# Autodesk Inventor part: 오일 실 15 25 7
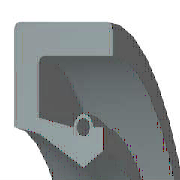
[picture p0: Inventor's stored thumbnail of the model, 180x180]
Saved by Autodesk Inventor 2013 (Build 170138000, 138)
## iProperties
IsCustomPart: 1
Created: 2012-02
Part Number: 오일 실 15 25 7
Material: 고무
Description: 오일 실 - 스프링 장착, 금속 케이스 SM
Document SubType Name: Modeling
Standard: JIS B 2402
Designer: mdu-01
Standards Organization: JIS
Language: ko-KR
Size Designation: 15 25 7 A
Categories: <MemberInstance><Categories><Category DisplayName="샤프트 부품" InternalName="7f7aeb1f-a693-4053-b835-cee3144e0d98" Mnemonic="SHFT"><Category DisplayName="실링" Intern
Density: 0.93 g/cm^3
Author: mdu-01
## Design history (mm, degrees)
body "Solid1"
revolve "회전1" stored, may be unused: angle "d33" = 360 deg
fillet "모깎기1" dims "d34" = 0.35 (= 0.05 x b)
chamfer "모따기1" distance "d35" = 0.7 (= 0.1 x b); stored, may be unused: second distance "d36" = 0.35 (= 0.05 x b), angle "d41" = 45 deg
sketch "스케치2"
  geometry: L1 (8.714, -5.158)-(9.184, -7); L2 (8.214, -4.55)-(8.714, -5.158); L3 (7.5, -1.75)-(8.214, -4.55); L4 (8.167, -0.875)-(7.5, -1.75); L5 (9.284, -0.875)-(8.167, -0.875); L6 (9.284, -1.575)-(9.284, -0.875); L7 (9.284, -5.25)-(9.284, -2.975); L8 (10.5, -5.25)-(9.284, -5.25); L9 (11.5, -1.75)-(10.5, -5.25); L10 (11.5, 0)-(11.5, -1.75); L11 (12.5, 0)-(11.5, 0); L12 (12.5, -7)-(12.5, 0); L13 (9.184, -7)-(12.5, -7); L14 (0, -9.6)-(0, 1.6) reference; L15 (28, 0)-(14, 0) reference; A1 r 0.7 centre (9.284, -2.275) between (9.284, -2.975) and (9.284, -1.575)
  constraints: 26 end point, 4 horizontal, 4 vertical, 2 point on circle, 1 centre point, 1 collinear, 1 parallel
  dimensions: "d2" = 7 distance of L12.start L11.start (= b); "d4" = 0.875 vertical distance of L10.start L5.start (= 0.125 x b); "d6" = 1 distance of L11.start L10.start (= 0.1 x dd - 0.1 x Diam); "d8" = 1.75 distance of L10.start L9.start (= 0.25 x b); "d10" = 1.75 vertical distance of L8.start L1.end (= 0.25 x b); "d12" = 1 horizontal distance of L9.start L8.start (= 0.1 x dd - 0.1 x Diam); "d14" = 0.7 radius of A1 (= 0.1 x b); "d16" = 0 horizontal distance of A1.centre L7.end; "d18" = 0.7 distance of L6.start L5.start (= 0.1 x b); "d20" = 0.66667 horizontal distance of L4.start L3.start (= 0.0666667 x dd - 0.0666667 x Diam); "d22" = 0.1 horizontal distance of L7.start L1.end (= 0.01 x dd - 0.01 x Diam); "d24" = 0.875 vertical distance of L4.start L3.start (= 0.125 x b); "d26" = 2.8 vertical distance of L3.start L2.start (= 0.4 x b); "d28" = 0.71429 horizontal distance of L3.start L2.start (= 0.0714286 x dd - 0.0714286 x Diam); "d30" = 1.84211 vertical distance of L1.start L1.end (= 0.263158 x b); "d32" = 0.5 horizontal distance of L2.start L1.start (= 0.05 x dd - 0.05 x Diam); "d37" = 0 distance between parallel lines of L15 L11; "d38" = 12.5 distance between parallel lines of L14 L12 (= 0.5 x dd); "d39" = 7.5 distance from line of L14 L3.start (= 0.5 x Diam)
other parameters: "dd" = 25 [user parameter; used in 7 equation terms], "Diam" = 15 [user parameter; used in 7 equation terms], "b" = 7 [user parameter; used in 12 equation terms], "d1" = 8 (derived), "d3" = 1 (derived), "d5" = 2 (derived), "d7" = 2 (derived), "d9" = 2 (derived), "d11" = 2 (derived), "d13" = 0.8 (derived), "d15" = 0 (derived), "d17" = 0.8 (derived), "d19" = 1.33333 (derived), "d21" = 0.2 (derived), "d23" = 1 (derived), "d25" = 3.2 (derived), "d27" = 1.42857 (derived), "d29" = 2.10526 (derived), "d31" = 1 (derived), "d40" = 0
